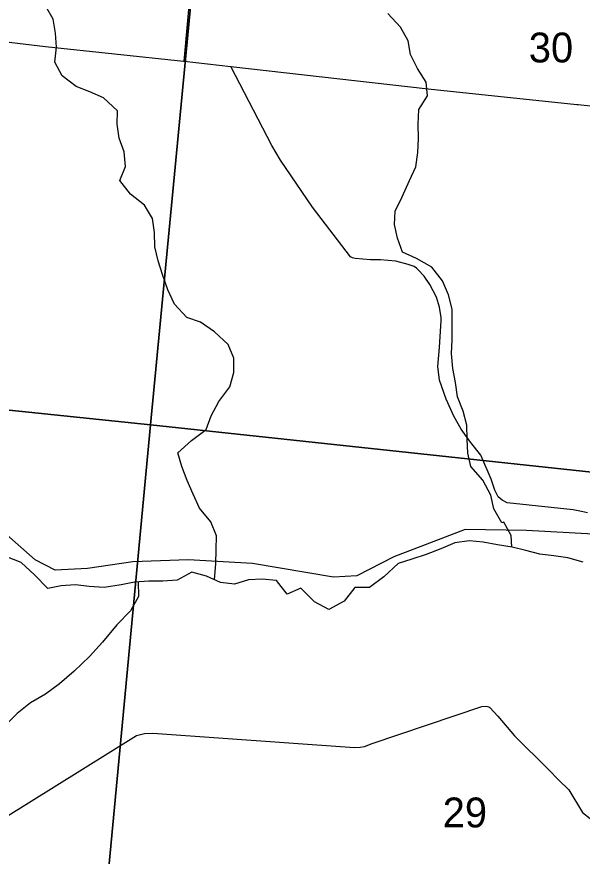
# Model space of a CAD drawing. Extents: x 44.2 to 78.2, y 4.5 to 26.5.
# Drawn here: x 47.352 to 48.145, y 21.309 to 22.487 of the extents above; entities that cross this region are included whole.
import ezdxf

# ---------------------------------------------------------------- set-up
doc = ezdxf.new("R2010")
doc.units = 0
for name, color, linetype in [('GM_X_City_Street', 7, 'Continuous'), ('GM_X_County_Road', 7, 'Continuous'), ('GM_X_Minor_River', 7, 'Continuous'), ('GM_X_Rail_Line', 7, 'Continuous'), ('GM_X_Section', 7, 'Continuous'), ('GM_X_Section_Text', 7, 'Continuous')]:
    doc.layers.add(name, color=color, linetype=linetype)

msp = doc.modelspace()

# ---------------------------------------------------------------- linework, layer by layer
at = {"layer": 'GM_X_City_Street'}
for points in [[(47.5871, 22.4241), (47.6104, 22.6841), (47.6324, 22.9195), (47.6335, 22.9315), (47.6604, 23.2001), (47.6743, 23.3461), (47.6796, 23.42), (47.6988, 23.621), (47.7094, 23.7363), (47.7207, 23.8665), (47.7293, 23.9658), (47.7531, 24.2297), (47.7926, 24.645), (47.8235, 24.975), (47.8417, 25.154), (47.8427, 25.1627), (47.8456, 25.1682), (47.8502, 25.1739), (47.8852, 25.2095), (47.9138, 25.2411), (47.9159, 25.2442), (47.9166, 25.2462), (47.9174, 25.2513)], [(48.153, 21.7907), (48.1443, 21.7927), (48.1326, 21.7948), (48.0401, 21.8048), (48.0329, 21.8084), (48.0277, 21.8134), (48.0229, 21.8226), (48.0175, 21.8379), (48.0033, 21.8716), (47.9888, 21.8901), (47.9755, 21.9082), (47.9651, 21.9263), (47.9546, 21.95), (47.9452, 21.9768), (47.9428, 21.9959), (47.9452, 22.0228), (47.9475, 22.0604), (47.9475, 22.0646), (47.945, 22.0792), (47.9408, 22.0932), (47.9316, 22.1109), (47.9239, 22.1228), (47.9153, 22.1318), (47.913, 22.134), (47.9096, 22.1363), (47.9012, 22.1392), (47.884, 22.1436), (47.8624, 22.1455), (47.8483, 22.1454), (47.8267, 22.1477), (47.8232, 22.1483), (47.8203, 22.1497), (47.7672, 22.2194), (47.7221, 22.2856), (47.7099, 22.306), (47.6526, 22.4167)], [(47.256, 21.3146), (47.5198, 21.4787), (47.5312, 21.4811), (47.543, 21.4816), (47.8259, 21.4616), (47.834, 21.462), (47.84, 21.4632), (47.8507, 21.4672), (48.0047, 21.5192), (48.0108, 21.5195), (48.0143, 21.5188), (48.0157, 21.5178), (48.0272, 21.5058), (48.0505, 21.4779), (48.098, 21.4309), (48.1128, 21.4158), (48.1269, 21.4021), (48.146, 21.3706), (48.1568, 21.3619), (48.1684, 21.3541), (48.1815, 21.3477), (48.1924, 21.3433), (48.2128, 21.3406)]]:
    msp.add_lwpolyline(points, dxfattribs=at)
at = {"layer": 'GM_X_County_Road'}
for points in [[(46.5657, 22.4), (46.8345, 22.372), (46.8546, 22.3709), (46.8835, 22.3727), (46.9098, 22.3753), (46.9174, 22.3767), (46.9277, 22.3818), (47.0656, 22.4656), (47.0778, 22.4711), (47.0904, 22.4728), (47.1189, 22.4746), (47.2073, 22.4669), (47.3922, 22.445), (47.586, 22.4242), (47.5871, 22.4241)], [(47.5871, 22.4241), (47.6526, 22.4167), (47.9293, 22.3853), (48.1379, 22.3635)], [(48.1379, 22.3635), (48.1399, 22.3633), (48.1913, 22.3579)]]:
    msp.add_lwpolyline(points, dxfattribs=at)
at = {"layer": 'GM_X_Minor_River'}
for points in [[(47.6294, 21.6968), (47.6313, 21.7199), (47.6317, 21.7389), (47.6325, 21.7583), (47.6245, 21.7781), (47.6085, 21.7971), (47.5993, 21.8169), (47.5913, 21.8363), (47.5837, 21.8557), (47.578, 21.8748), (47.5974, 21.8923), (47.6176, 21.9075), (47.6248, 21.9269), (47.6355, 21.947), (47.6511, 21.9676), (47.6568, 21.9874), (47.6568, 22.0075), (47.6488, 22.0269), (47.6294, 22.0448), (47.61, 22.0581), (47.5905, 22.0646), (47.5734, 22.0836), (47.5642, 22.1034), (47.5566, 22.1251), (47.5505, 22.1441), (47.5459, 22.1639), (47.5452, 22.184), (47.5425, 22.2034), (47.5311, 22.2225), (47.5116, 22.2377), (47.4968, 22.2567), (47.5044, 22.2765), (47.5025, 22.297), (47.4956, 22.3164), (47.4929, 22.3358), (47.4933, 22.3548), (47.4739, 22.3727), (47.4544, 22.3811), (47.4354, 22.3887), (47.4156, 22.4039), (47.4056, 22.4229), (47.4076, 22.4438), (47.4064, 22.4636), (47.403, 22.483), (47.3923, 22.502)], [(48.0465, 21.7425), (48.0456, 21.7591), (48.0354, 21.7777), (48.0326, 21.7766), (48.0216, 21.7964), (48.0174, 21.8154), (48.006, 21.8367), (47.9892, 21.8557), (47.985, 21.8747), (47.9842, 21.8941), (47.9835, 21.9139), (47.9785, 21.9333), (47.9705, 21.9535), (47.9675, 21.9737), (47.964, 21.9934), (47.9621, 22.0144), (47.9629, 22.0334), (47.9629, 22.0764), (47.9579, 22.0965), (47.9495, 22.1163), (47.9343, 22.1353), (47.9129, 22.1475), (47.8931, 22.1563), (47.8863, 22.176), (47.8821, 22.1951), (47.8832, 22.2141), (47.8927, 22.2342), (47.903, 22.2567), (47.9118, 22.2761), (47.9148, 22.2962), (47.9156, 22.316), (47.9152, 22.3358), (47.916, 22.3567), (47.9285, 22.3757), (47.9266, 22.3948), (47.9141, 22.4142), (47.9045, 22.4336), (47.9011, 22.453), (47.8904, 22.472), (47.8729, 22.491)], [(48.1466, 21.7214), (48.1252, 21.7279), (48.1058, 21.7306), (48.086, 21.7328), (48.0662, 21.7378), (48.0471, 21.7424), (48.0265, 21.7458), (48.0063, 21.7496), (47.9869, 21.7515), (47.9667, 21.7488), (47.9469, 21.7405), (47.9267, 21.7325), (47.9065, 21.7256), (47.8874, 21.7199), (47.8669, 21.7009), (47.847, 21.6861), (47.8265, 21.6861), (47.8112, 21.6667), (47.7899, 21.6552), (47.7697, 21.6659), (47.7506, 21.6849), (47.7316, 21.6769), (47.7167, 21.6959), (47.6965, 21.6978), (47.6771, 21.6967), (47.6576, 21.6906), (47.6378, 21.6929), (47.6184, 21.702), (47.5978, 21.7074), (47.5772, 21.6963), (47.557, 21.6948), (47.5372, 21.6948), (47.5174, 21.6937), (47.4983, 21.6899), (47.4747, 21.6861), (47.4537, 21.6876), (47.4343, 21.6899), (47.4145, 21.6883), (47.3954, 21.6845), (47.3771, 21.7036), (47.3581, 21.7211)], [(47.3581, 21.7211), (47.3367, 21.7294)], [(47.5224, 21.694), (47.5227, 21.6735), (47.5117, 21.6533), (47.4922, 21.6336), (47.4724, 21.6096), (47.4541, 21.5894), (47.4324, 21.5689), (47.4118, 21.551), (47.3924, 21.5365), (47.3714, 21.5244), (47.3524, 21.5095), (47.3329, 21.4897), (47.3177, 21.4703), (47.2967, 21.4551), (47.2773, 21.4452), (47.2582, 21.4315), (47.2422, 21.4121), (47.2224, 21.3962), (47.203, 21.3828), (47.1839, 21.3752), (47.1656, 21.3612)]]:
    msp.add_lwpolyline(points, dxfattribs=at)
at = {"layer": 'GM_X_Rail_Line'}
msp.add_lwpolyline([(48.1614, 21.7609), (48.0675, 21.7662), (47.981, 21.7675), (47.8811, 21.7289), (47.8292, 21.7022), (47.7964, 21.7005), (47.6827, 21.7196), (47.5927, 21.7249), (47.5151, 21.7222), (47.4512, 21.7129), (47.406, 21.7102), (47.3778, 21.7248), (47.3295, 21.7673)], dxfattribs=at)
at = {"layer": 'GM_X_Section'}
for points in [[(46.6305, 23.0253), (47.6368, 22.9304), (47.5395, 21.914), (46.5345, 22.0186)], [(47.6368, 22.9304), (48.6514, 22.8354), (48.5512, 21.8058), (47.5395, 21.914)], [(47.5395, 21.914), (47.4461, 20.9212), (46.4385, 21.0127), (46.5345, 22.0186)], [(48.5512, 21.8058), (48.4564, 20.8172), (47.4461, 20.9212), (47.5395, 21.914)]]:
    msp.add_lwpolyline(points, close=True, dxfattribs=at)

# ---------------------------------------------------------------- texts
at = {"layer": 'GM_X_Section_Text'}
for s, p in [('30', (48.0705, 22.4225)), ('29', (47.9497, 21.3496))]:
    msp.add_text(s, height=0.04186, rotation=0, dxfattribs=at).set_placement(p)

doc.saveas('drawing.dxf')
